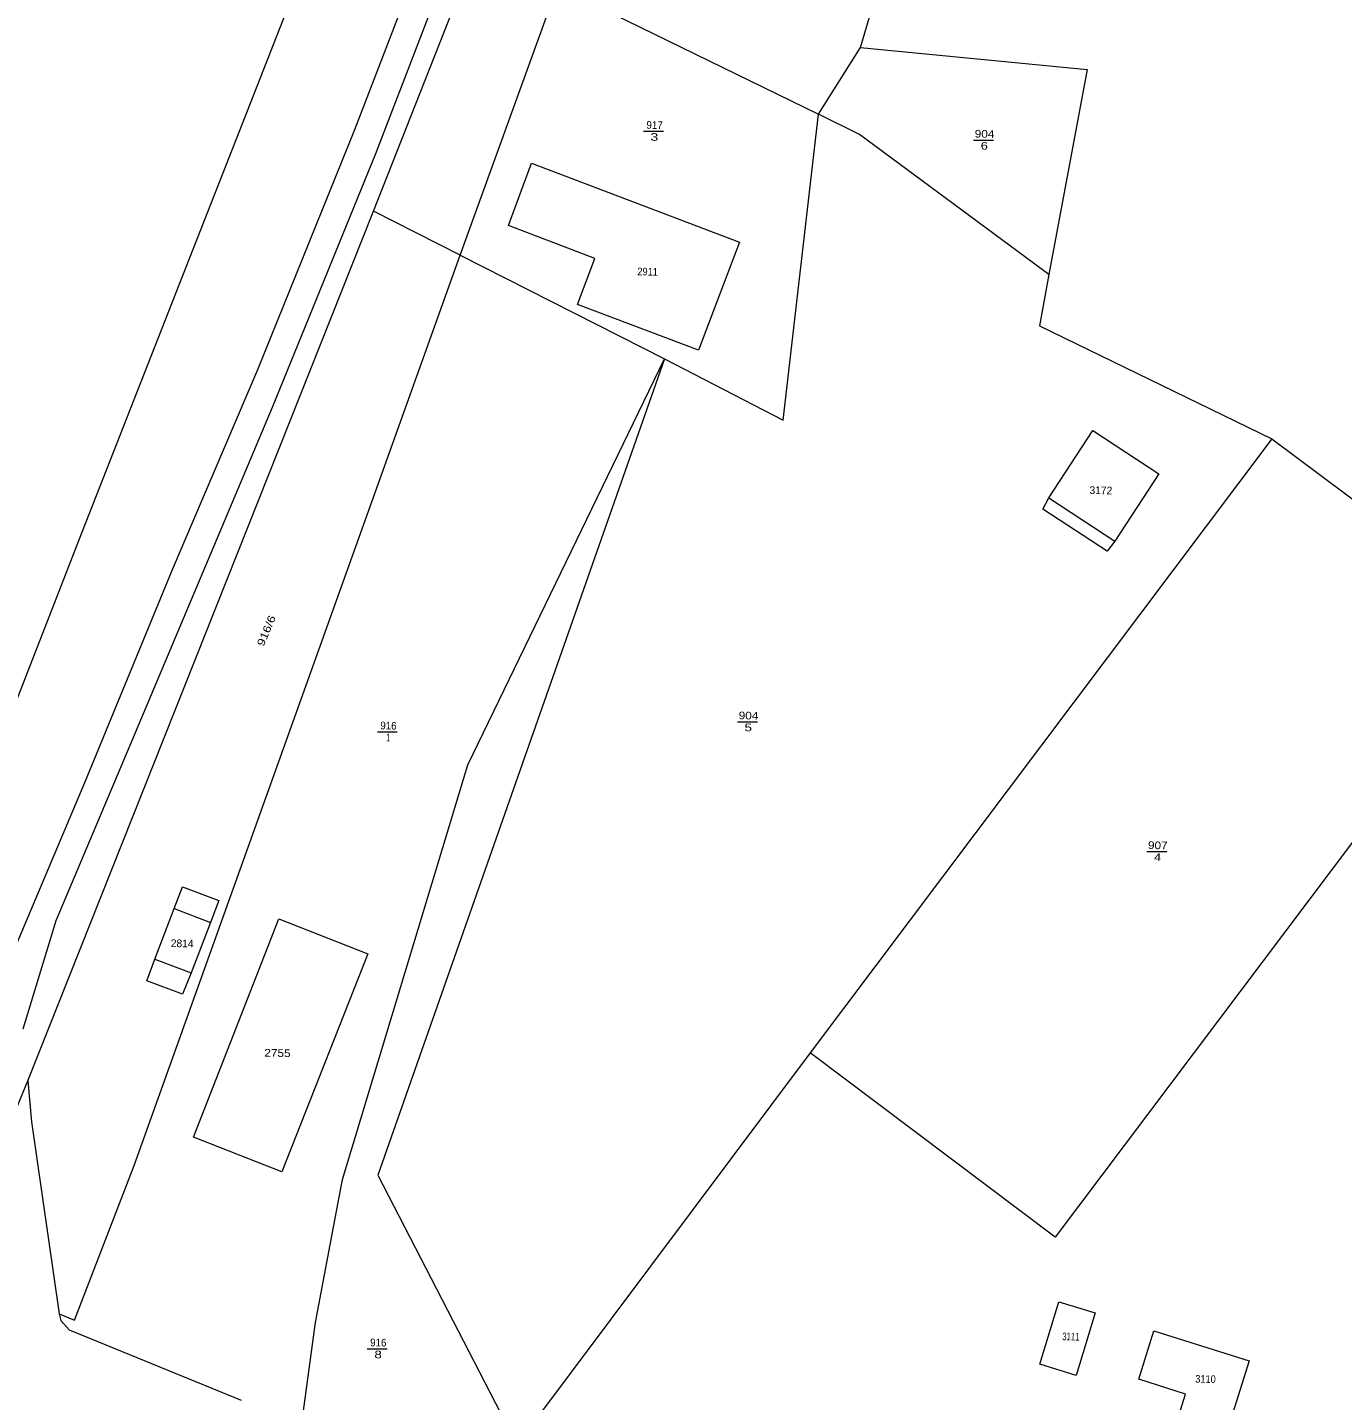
# Model space of a CAD drawing. Extents: x -843400 to -842830, y -1002860 to -1002082.
# Drawn here: x -843269.1 to -843097.6, y -1002523 to -1002343.9 of the extents above; entities that cross this region are included whole.
import ezdxf
from ezdxf.enums import TextEntityAlignment as Align

# ---------------------------------------------------------------- set-up
doc = ezdxf.new("R2010")
doc.units = 0
doc.header["$LTSCALE"] = 0.4
for name, color, linetype, lineweight in [('32', 7, 'Continuous', 13), ('34', 7, 'Continuous', 13), ('35', 7, 'Continuous', 13), ('36', 7, 'Continuous', 13), ('38', 7, 'Continuous', 13), ('40', 7, 'Continuous', 13), ('43', 7, 'Continuous', 13)]:
    doc.layers.add(name, color=color, linetype=linetype, lineweight=lineweight)

msp = doc.modelspace()

# ---------------------------------------------------------------- linework, layer by layer
at = {"layer": '32'}
msp.add_line((-843106.81, -1002397.6), (-843167.05, -1002477.66), dxfattribs=at)
for points in [[(-843212.69, -1002373.63), (-843186.05, -1002387.15), (-843170.56, -1002395.13), (-843165.96, -1002355.23)], [(-843135.89, -1002376.13), (-843160.61, -1002357.89), (-843165.96, -1002355.23)], [(-843269.09, -1002481.33), (-843268.59, -1002486.66), (-843264.98, -1002511.71), (-843262.99, -1002512.53), (-843255.19, -1002492.36), (-843212.69, -1002373.63), (-843224, -1002367.89)], [(-843233.392, -1002526.274), (-843231.55, -1002512.84), (-843228.02, -1002494.21), (-843211.7, -1002440.09), (-843186.05, -1002387.15), (-843223.42, -1002493.62), (-843207.38, -1002524.72), (-843208.79, -1002526.68)], [(-843074.76, -1002421.55), (-843135.09, -1002501.71), (-843167.05, -1002477.66), (-843203.39, -1002526.24)]]:
    msp.add_lwpolyline(points, dxfattribs=at)
at = {"layer": '34'}
for p, q in [((-843188.768, -1002357.454), (-843186.172, -1002357.454)), ((-843145.73, -1002358.607), (-843143.134, -1002358.607)), ((-843223.478, -1002435.789), (-843220.882, -1002435.789)), ((-843176.517, -1002434.478), (-843173.921, -1002434.478)), ((-843123.134, -1002451.404), (-843120.538, -1002451.404)), ((-843224.799, -1002516.256), (-843222.203, -1002516.256))]:
    msp.add_line(p, q, dxfattribs=at)
at = {"layer": '36'}
for p, q in [((-843212.69, -1002373.63), (-843199.99, -1002338.57)), ((-843135.9, -1002405.28), (-843127.31, -1002410.92)), ((-843249.99, -1002458.86), (-843245.26, -1002460.66)), ((-843252.49, -1002465.44), (-843247.77, -1002467.24))]:
    msp.add_line(p, q, dxfattribs=at)
msp.add_lwpolyline([(-843264.98, -1002511.71), (-843264.75, -1002512.57), (-843263.68, -1002513.78), (-843251.01, -1002518.97), (-843241.25, -1002522.98)], dxfattribs=at)
at = {"layer": '38'}
for points in [[(-843203.36, -1002361.64), (-843176.25, -1002371.92), (-843179.21, -1002379.73), (-843181.61, -1002386.04), (-843197.38, -1002380.05), (-843195.1, -1002374.05), (-843206.4, -1002369.76)], [(-843136.71, -1002406.74), (-843135.9, -1002405.28), (-843130.17, -1002396.5), (-843121.54, -1002402.13), (-843127.31, -1002410.92), (-843128.31, -1002412.22)], [(-843248.9, -1002456.01), (-843244.18, -1002457.81), (-843245.26, -1002460.66), (-843247.77, -1002467.24), (-843248.9, -1002470.03), (-843253.57, -1002468.26), (-843252.49, -1002465.44), (-843249.99, -1002458.86)], [(-843236.34, -1002460.2), (-843224.74, -1002464.77), (-843235.93, -1002493.21), (-843247.46, -1002488.68)], [(-843134.59, -1002510.14), (-843129.85, -1002511.59), (-843132.34, -1002519.74), (-843137.1, -1002518.26)], [(-843122.22, -1002513.94), (-843109.79, -1002517.83), (-843113.37, -1002529.3), (-843119.68, -1002527.32), (-843118.09, -1002522.18), (-843124.19, -1002520.23)]]:
    msp.add_lwpolyline(points, close=True, dxfattribs=at)
at = {"layer": '40'}
msp.add_lwpolyline([(-843160.48, -1002346.53), (-843130.91, -1002349.42), (-843135.89, -1002376.13), (-843137.14, -1002382.83), (-843106.81, -1002397.6), (-843074.76, -1002421.55), (-843056.97, -1002434.86), (-843014.68, -1002358.16), (-842987.77, -1002367.07), (-842967.67, -1002372.97), (-842947.11, -1002381.03), (-842989.7, -1002460.5), (-842985.04, -1002466.11), (-842976.06, -1002481.3), (-842960.58, -1002507.03), (-842950.97, -1002527.42), (-842942.15, -1002541.29), (-842902.4, -1002544.91), (-842896.82, -1002551.16), (-842896.49, -1002560.21), (-842897.95, -1002605.27), (-842896.46, -1002622.59)], dxfattribs=at)
at = {"layer": '43'}
for points in [[(-843217.19, -1002333.18), (-843226.47, -1002357.28), (-843239.13, -1002388.59), (-843250.24, -1002414.68), (-843261.68, -1002442.44), (-843271.91, -1002466.67), (-843277.55, -1002472.17), (-843281.73, -1002480.82), (-843284.3, -1002490.53), (-843294.657, -1002521.152), (-843302.333, -1002519.323), (-843301.23, -1002516.16), (-843300.52, -1002513.26), (-843299.93, -1002510.29), (-843298.98, -1002505.38), (-843298.14, -1002502.05), (-843296.89, -1002499.02), (-843283.93, -1002465.53), (-843273.11, -1002438.25), (-843261.95, -1002409.61), (-843251.14, -1002382.13), (-843240.02, -1002353.81), (-843228.82, -1002325.16)], [(-843211.81, -1002329.41), (-843223.74, -1002360.42), (-843237.19, -1002393.48), (-843255.79, -1002437.59), (-843265.4, -1002460.44), (-843269.723, -1002474.597)], [(-843271.39, -1002486.91), (-843269.09, -1002481.33), (-843224, -1002367.89), (-843210.41, -1002333.47)], [(-843199.99, -1002338.57), (-843165.96, -1002355.23), (-843160.48, -1002346.53), (-843157.16, -1002335.34)]]:
    msp.add_lwpolyline(points, dxfattribs=at)

# ---------------------------------------------------------------- texts
at = {"layer": '34'}
for s, rotation, width, p in [('917', 358.734, 0.95, (-843187.339, -1002357.1573)), ('904', 358.734, 1.15, (-843144.3015, -1002358.3096)), ('3', 358.734, 1.4, (-843187.3735, -1002358.7065)), ('6', 358.734, 1.25, (-843144.3345, -1002359.8594)), ('916/6', 67.057, 1.25, (-843237.5063, -1002422.8024)), ('904', 358.734, 1.15, (-843175.088, -1002434.1806)), ('916', 358.734, 0.95, (-843222.0485, -1002435.4918)), ('1', 358.734, 0.7, (-843222.083, -1002437.0419)), ('5', 358.734, 1.35, (-843175.1215, -1002435.73)), ('907', 358.734, 1.15, (-843121.7055, -1002451.1061)), ('4', 358.734, 1.25, (-843121.738, -1002452.6564)), ('916', 358.734, 0.95, (-843223.37, -1002515.9588)), ('8', 358.734, 1.3, (-843223.404, -1002517.5086))]:
    msp.add_text(s, height=1, rotation=rotation, dxfattribs=dict(at, width=width)).set_placement(p, align=Align.CENTER)
at = {"layer": '35'}
for s, width, p in [('2911', 0.9, (-843188.2465, -1002376.2772)), ('2755', 1.15, (-843236.524, -1002478.1919)), ('3111', 0.75, (-843133.044, -1002515.1748)), ('3110', 0.9, (-843115.483, -1002520.7047))]:
    msp.add_text(s, height=1, rotation=358.734, dxfattribs=dict(at, width=width)).set_placement(p, align=Align.CENTER)
for s, p in [('3172', (-843129.13, -1002404.8003)), ('2814', (-843248.9525, -1002463.895))]:
    msp.add_text(s, height=1, rotation=358.734, dxfattribs=at).set_placement(p, align=Align.CENTER)

doc.saveas('drawing.dxf')
